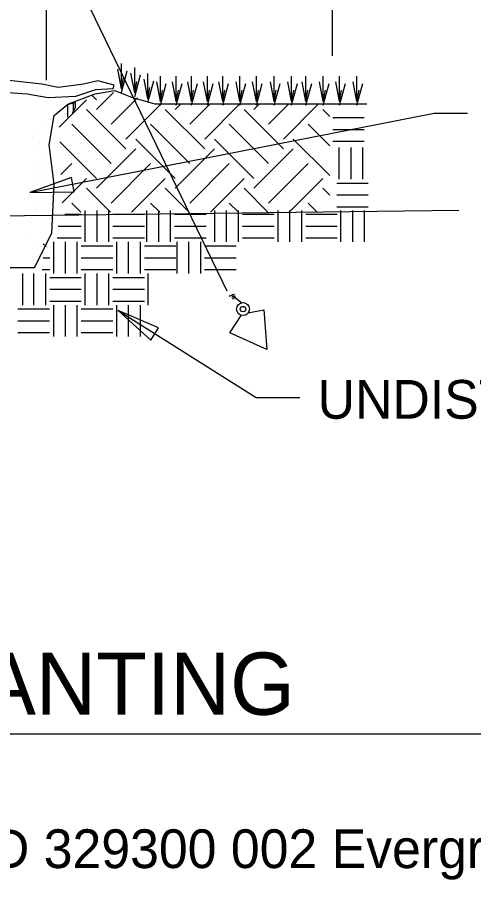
# Model space of a CAD drawing. Extents: x 10082 to 10257, y 10014 to 10069.
# Drawn here: x 10139.41 to 10147.66, y 10014.41 to 10029.99 of the extents above; entities that cross this region are included whole.
import ezdxf

# ---------------------------------------------------------------- set-up
doc = ezdxf.new("R2010")
doc.units = 0
for name, color, linetype in [('Default', 7, 'Continuous'), ('G-ANNO-CELL', 7, 'Continuous'), ('G-ANNO-TEXT', 7, 'Continuous'), ('G-DETL-GRID', 7, 'Continuous'), ('G-DETL-LINE', 7, 'Continuous'), ('G-DETL-OTLN', 7, 'Continuous'), ('G-DETL-PATT', 7, 'Continuous'), ('G-DETL-TEXT', 7, 'Continuous')]:
    doc.layers.add(name, color=color, linetype=linetype)

msp = doc.modelspace()

# ---------------------------------------------------------------- linework, layer by layer
at = {"layer": 'Default'}
for p, q in [((10139.933, 10028.854), (10139.933, 10030.362)), ((10145.108, 10029.298), (10145.108, 10030.362)), ((10139.636, 10026.823), (10146.946, 10028.258)), ((10146.946, 10028.258), (10147.547, 10028.258)), ((10138.67, 10026.397), (10147.389, 10026.507)), ((10141.228, 10024.692), (10143.727, 10023.12)), ((10143.727, 10023.12), (10144.513, 10023.12))]:
    msp.add_line(p, q, dxfattribs=at)
for points in [[(10140.433, 10026.839), (10140.384, 10027.096), (10139.636, 10026.823)], [(10141.82, 10024.16), (10141.961, 10024.38), (10141.228, 10024.692)]]:
    msp.add_lwpolyline(points, close=True, dxfattribs=at)
at = {"layer": 'G-ANNO-TEXT'}
for p, q in [((10120.67, 10017.044), (10152.453, 10017.044)), ((10120.67, 10017.044), (10152.453, 10017.044)), ((10122.114, 10017.044), (10151.008, 10017.044)), ((10122.114, 10017.044), (10151.008, 10017.044))]:
    msp.add_line(p, q, dxfattribs=at)
at = {"layer": 'G-DETL-LINE'}
for p, q in [((10137.65, 10036.497), (10143.193, 10025.048)), ((10141.291, 10028.7), (10141.224, 10029.053)), ((10141.291, 10028.7), (10141.291, 10029.158)), ((10141.53, 10028.628), (10141.53, 10029.086)), ((10141.291, 10028.633), (10141.396, 10029.024)), ((10141.291, 10028.7), (10141.329, 10028.901)), ((10141.53, 10028.628), (10141.462, 10028.981)), ((10141.53, 10028.561), (10141.635, 10028.952)), ((10141.769, 10028.52), (10141.769, 10028.978)), ((10141.995, 10028.472), (10141.995, 10028.93)), ((10142.281, 10028.472), (10142.281, 10028.93)), ((10142.557, 10028.472), (10142.557, 10028.93)), ((10142.843, 10028.472), (10142.843, 10028.93)), ((10143.12, 10028.472), (10143.12, 10028.93)), ((10143.433, 10028.472), (10143.433, 10028.93)), ((10143.729, 10028.472), (10143.729, 10028.93)), ((10144.052, 10028.472), (10144.052, 10028.93)), ((10144.367, 10028.472), (10144.367, 10028.93)), ((10144.624, 10028.472), (10144.624, 10028.93)), ((10144.939, 10028.472), (10144.939, 10028.93)), ((10145.233, 10028.472), (10145.233, 10028.93)), ((10145.548, 10028.472), (10145.548, 10028.93)), ((10141.53, 10028.628), (10141.567, 10028.829)), ((10141.769, 10028.52), (10141.701, 10028.873)), ((10141.769, 10028.454), (10141.874, 10028.844)), ((10141.769, 10028.52), (10141.806, 10028.721)), ((10141.995, 10028.472), (10141.928, 10028.825)), ((10141.995, 10028.406), (10142.1, 10028.796)), ((10142.281, 10028.472), (10142.214, 10028.825)), ((10142.281, 10028.406), (10142.386, 10028.796)), ((10142.557, 10028.472), (10142.49, 10028.825)), ((10142.557, 10028.406), (10142.662, 10028.796)), ((10142.843, 10028.472), (10142.775, 10028.825)), ((10142.843, 10028.406), (10142.948, 10028.796)), ((10143.12, 10028.472), (10143.052, 10028.825)), ((10143.12, 10028.406), (10143.225, 10028.796)), ((10143.433, 10028.472), (10143.365, 10028.825)), ((10143.433, 10028.406), (10143.537, 10028.796)), ((10143.729, 10028.472), (10143.661, 10028.825)), ((10143.729, 10028.406), (10143.834, 10028.796)), ((10144.052, 10028.472), (10143.985, 10028.825)), ((10144.052, 10028.406), (10144.157, 10028.796)), ((10144.367, 10028.472), (10144.3, 10028.825)), ((10144.367, 10028.406), (10144.472, 10028.796)), ((10144.624, 10028.472), (10144.557, 10028.825)), ((10144.624, 10028.406), (10144.729, 10028.796)), ((10144.939, 10028.472), (10144.872, 10028.825)), ((10144.939, 10028.406), (10145.044, 10028.796)), ((10145.233, 10028.472), (10145.165, 10028.825)), ((10145.233, 10028.406), (10145.338, 10028.796)), ((10145.548, 10028.472), (10145.48, 10028.825)), ((10145.548, 10028.406), (10145.653, 10028.796)), ((10141.995, 10028.472), (10142.033, 10028.673)), ((10142.281, 10028.472), (10142.319, 10028.673)), ((10142.557, 10028.472), (10142.595, 10028.673)), ((10142.843, 10028.472), (10142.88, 10028.673)), ((10143.12, 10028.472), (10143.157, 10028.673)), ((10143.433, 10028.472), (10143.47, 10028.673)), ((10143.729, 10028.472), (10143.766, 10028.673)), ((10144.052, 10028.472), (10144.09, 10028.673)), ((10144.367, 10028.472), (10144.405, 10028.673)), ((10144.624, 10028.472), (10144.662, 10028.673)), ((10144.939, 10028.472), (10144.977, 10028.673)), ((10145.233, 10028.472), (10145.27, 10028.673)), ((10145.548, 10028.472), (10145.585, 10028.673))]:
    msp.add_line(p, q, dxfattribs=at)
for points in [[(10143.326, 10024.989), (10143.234, 10024.947)], [(10143.34, 10024.961), (10143.28, 10024.929)], [(10143.357, 10024.932), (10143.297, 10024.9)], [(10143.467, 10024.827), (10143.3, 10024.958)], [(10143.864, 10024.703), (10143.917, 10023.988), (10143.251, 10024.292), (10143.456, 10024.601)], [(10143.573, 10024.65), (10143.864, 10024.703)]]:
    msp.add_lwpolyline(points, dxfattribs=at)
for radius in [0.117, 0.0496]:
    msp.add_circle((10143.488, 10024.718), radius, dxfattribs=at)
at = {"layer": 'G-DETL-OTLN'}
for p, q in [((10140.333, 10028.427), (10140.813, 10028.607)), ((10140.813, 10028.607), (10141.173, 10028.667)), ((10141.173, 10028.667), (10141.473, 10028.547)), ((10140.074, 10028.217), (10140.322, 10028.421)), ((10141.473, 10028.547), (10141.896, 10028.427)), ((10141.896, 10028.427), (10145.726, 10028.427)), ((10139.986, 10027.686), (10140.074, 10028.217)), ((10140.074, 10026.977), (10139.986, 10027.686)), ((10140.029, 10026.091), (10140.074, 10026.977)), ((10139.72, 10025.472), (10140.029, 10026.091)), ((10136.884, 10025.472), (10139.72, 10025.472))]:
    msp.add_line(p, q, dxfattribs=at)
msp.add_lwpolyline([(10136.661, 10029.223), (10136.7, 10028.984), (10137.357, 10028.904), (10137.776, 10028.865), (10138.594, 10028.725), (10139.05, 10028.645), (10139.587, 10028.606), (10139.967, 10028.545), (10140.465, 10028.565), (10140.824, 10028.684), (10141.141, 10028.705), (10141.161, 10028.764), (10140.864, 10028.844), (10140.603, 10028.785), (10140.145, 10028.725), (10139.848, 10028.785), (10139.31, 10028.844), (10138.812, 10028.904), (10138.274, 10029.025), (10137.657, 10029.025), (10137.08, 10029.143), (10136.879, 10029.203)], close=True, dxfattribs=at)
at = {"layer": 'G-DETL-PATT'}
for p, q in [((10140.838, 10028.503), (10140.763, 10028.578)), ((10140.838, 10028.325), (10141.144, 10028.631)), ((10140.164, 10028.007), (10140.66, 10028.503)), ((10140.322, 10028.185), (10140.322, 10028.421)), ((10140.333, 10028.42), (10140.451, 10028.453)), ((10140.423, 10028.298), (10140.423, 10028.445)), ((10140.451, 10028.453), (10140.451, 10028.353)), ((10141.104, 10028.058), (10141.581, 10028.535)), ((10141.371, 10027.792), (10142, 10028.42)), ((10142.261, 10028.325), (10142.355, 10028.42)), ((10142.528, 10028.058), (10142.889, 10028.42)), ((10142.795, 10027.792), (10143.423, 10028.42)), ((10143.685, 10028.325), (10143.779, 10028.42)), ((10143.951, 10028.058), (10144.313, 10028.42)), ((10144.218, 10027.792), (10144.847, 10028.42)), ((10140.451, 10028.353), (10140.399, 10028.251)), ((10141.371, 10027.614), (10140.66, 10028.325)), ((10142.795, 10027.614), (10142.083, 10028.325)), ((10144.218, 10027.614), (10143.507, 10028.325)), ((10145.056, 10028.2), (10144.93, 10028.325)), ((10145.109, 10028.18), (10145.68, 10028.18)), ((10139.851, 10027.999), (10139.851, 10027.999)), ((10141.104, 10027.347), (10140.393, 10028.058)), ((10142.528, 10027.347), (10141.816, 10028.058)), ((10143.951, 10027.347), (10143.24, 10028.058)), ((10145.056, 10027.666), (10144.663, 10028.058)), ((10145.109, 10027.966), (10145.68, 10027.966)), ((10139.683, 10027.817), (10139.683, 10027.817)), ((10139.753, 10027.906), (10139.753, 10027.906)), ((10140.067, 10027.786), (10140.067, 10027.786)), ((10142.261, 10027.08), (10141.549, 10027.792)), ((10143.685, 10027.08), (10142.973, 10027.792)), ((10145.056, 10027.132), (10144.396, 10027.792)), ((10139.799, 10027.71), (10139.799, 10027.71)), ((10139.996, 10027.753), (10139.996, 10027.753)), ((10140.838, 10027.08), (10140.174, 10027.743)), ((10145.109, 10027.752), (10145.68, 10027.752)), ((10145.228, 10027.068), (10145.228, 10027.639)), ((10145.442, 10027.068), (10145.442, 10027.639)), ((10145.656, 10027.068), (10145.656, 10027.639)), ((10139.724, 10027.596), (10139.724, 10027.596)), ((10140.838, 10026.902), (10141.549, 10027.614)), ((10142.261, 10026.902), (10142.973, 10027.614)), ((10143.685, 10026.902), (10144.396, 10027.614)), ((10139.799, 10027.355), (10139.799, 10027.355)), ((10139.822, 10027.473), (10139.822, 10027.473)), ((10139.961, 10027.327), (10139.961, 10027.327)), ((10140.197, 10027.151), (10140.393, 10027.347)), ((10141.104, 10026.635), (10141.816, 10027.347)), ((10142.528, 10026.635), (10143.24, 10027.347)), ((10143.951, 10026.635), (10144.663, 10027.347)), ((10139.953, 10027.167), (10139.953, 10027.167)), ((10139.684, 10027.088), (10139.684, 10027.088)), ((10139.754, 10027.159), (10139.754, 10027.159)), ((10139.926, 10027.111), (10139.926, 10027.111)), ((10140.06, 10027.052), (10140.06, 10027.052)), ((10140.067, 10027.039), (10140.067, 10027.039)), ((10140.218, 10026.638), (10140.66, 10027.08)), ((10141.474, 10026.47), (10142.083, 10027.08)), ((10142.897, 10026.47), (10143.507, 10027.08)), ((10144.321, 10026.47), (10144.93, 10027.08)), ((10139.883, 10026.87), (10139.883, 10026.87)), ((10141.091, 10026.47), (10140.66, 10026.902)), ((10142.515, 10026.47), (10142.083, 10026.902)), ((10143.938, 10026.47), (10143.507, 10026.902)), ((10145.056, 10026.776), (10144.93, 10026.902)), ((10145.183, 10026.997), (10145.753, 10026.997)), ((10139.901, 10026.73), (10139.901, 10026.73)), ((10140.038, 10026.818), (10140.038, 10026.818)), ((10145.183, 10026.783), (10145.753, 10026.783)), ((10139.76, 10026.609), (10139.76, 10026.609)), ((10140.051, 10026.58), (10140.051, 10026.58)), ((10140.557, 10026.47), (10140.393, 10026.635)), ((10141.981, 10026.47), (10141.816, 10026.635)), ((10143.404, 10026.47), (10143.24, 10026.635)), ((10144.828, 10026.47), (10144.663, 10026.635)), ((10145.183, 10026.569), (10145.753, 10026.569)), ((10139.749, 10026.533), (10139.749, 10026.533)), ((10139.755, 10026.412), (10139.755, 10026.412)), ((10139.756, 10026.477), (10139.756, 10026.477)), ((10139.987, 10026.405), (10139.987, 10026.405)), ((10140.266, 10026.432), (10140.564, 10026.432)), ((10140.635, 10025.933), (10140.635, 10026.503)), ((10140.849, 10025.933), (10140.849, 10026.503)), ((10141.063, 10025.933), (10141.063, 10026.503)), ((10141.134, 10026.432), (10141.704, 10026.432)), ((10141.75, 10025.933), (10141.75, 10026.503)), ((10141.964, 10025.933), (10141.964, 10026.503)), ((10142.178, 10025.933), (10142.178, 10026.503)), ((10142.249, 10026.432), (10142.82, 10026.432)), ((10142.978, 10025.933), (10142.978, 10026.503)), ((10143.192, 10025.933), (10143.192, 10026.503)), ((10143.406, 10025.933), (10143.406, 10026.503)), ((10143.478, 10026.432), (10144.048, 10026.432)), ((10144.122, 10025.933), (10144.122, 10026.503)), ((10144.336, 10025.933), (10144.336, 10026.503)), ((10144.55, 10025.933), (10144.55, 10026.503)), ((10144.621, 10026.432), (10145.191, 10026.432)), ((10145.257, 10025.933), (10145.257, 10026.503)), ((10145.471, 10025.933), (10145.471, 10026.503)), ((10145.685, 10025.933), (10145.685, 10026.503)), ((10139.65, 10026.276), (10139.65, 10026.276)), ((10140.055, 10026.334), (10140.055, 10026.334)), ((10140.068, 10026.292), (10140.068, 10026.292)), ((10140.069, 10026.357), (10140.069, 10026.357)), ((10140.147, 10026.218), (10140.564, 10026.218)), ((10141.134, 10026.218), (10141.704, 10026.218)), ((10142.249, 10026.218), (10142.82, 10026.218)), ((10143.478, 10026.218), (10144.048, 10026.218)), ((10144.621, 10026.218), (10145.191, 10026.218)), ((10139.655, 10025.972), (10139.655, 10025.972)), ((10139.979, 10025.986), (10139.979, 10025.986)), ((10140.065, 10025.362), (10140.065, 10025.933)), ((10140.126, 10026.004), (10140.564, 10026.004)), ((10140.278, 10025.362), (10140.278, 10025.933)), ((10140.492, 10025.362), (10140.492, 10025.933)), ((10141.134, 10026.004), (10141.704, 10026.004)), ((10141.205, 10025.362), (10141.205, 10025.933)), ((10141.419, 10025.362), (10141.419, 10025.933)), ((10141.633, 10025.362), (10141.633, 10025.933)), ((10142.249, 10026.004), (10142.82, 10026.004)), ((10142.295, 10025.362), (10142.295, 10025.933)), ((10142.509, 10025.362), (10142.509, 10025.933)), ((10142.723, 10025.362), (10142.723, 10025.933)), ((10143.478, 10026.004), (10144.048, 10026.004)), ((10144.621, 10026.004), (10145.191, 10026.004)), ((10139.72, 10025.863), (10139.72, 10025.863)), ((10139.812, 10025.893), (10139.812, 10025.893)), ((10139.927, 10025.849), (10139.877, 10025.899)), ((10139.948, 10025.84), (10139.948, 10025.84)), ((10140.564, 10025.861), (10141.134, 10025.861)), ((10141.704, 10025.861), (10142.275, 10025.861)), ((10142.794, 10025.861), (10143.364, 10025.861)), ((10139.685, 10025.675), (10139.685, 10025.675)), ((10139.755, 10025.665), (10139.755, 10025.665)), ((10139.875, 10025.647), (10139.993, 10025.647)), ((10140.564, 10025.647), (10141.134, 10025.647)), ((10141.704, 10025.647), (10142.275, 10025.647)), ((10142.794, 10025.647), (10143.364, 10025.647)), ((10139.793, 10025.593), (10139.793, 10025.593)), ((10139.509, 10024.792), (10139.509, 10025.362)), ((10139.708, 10024.792), (10139.708, 10025.362)), ((10139.854, 10025.434), (10139.993, 10025.434)), ((10139.922, 10024.792), (10139.922, 10025.362)), ((10140.564, 10025.434), (10141.134, 10025.434)), ((10140.635, 10024.792), (10140.635, 10025.362)), ((10140.849, 10024.792), (10140.849, 10025.362)), ((10141.063, 10024.792), (10141.063, 10025.362)), ((10141.704, 10025.434), (10142.275, 10025.434)), ((10141.776, 10024.792), (10141.776, 10025.362)), ((10142.794, 10025.434), (10143.364, 10025.434)), ((10139.993, 10025.291), (10140.564, 10025.291)), ((10141.134, 10025.291), (10141.704, 10025.291)), ((10139.993, 10025.077), (10140.564, 10025.077)), ((10141.134, 10025.077), (10141.704, 10025.077)), ((10139.993, 10024.863), (10140.564, 10024.863)), ((10141.134, 10024.863), (10141.704, 10024.863)), ((10139.418, 10024.721), (10139.988, 10024.721)), ((10140.065, 10024.221), (10140.065, 10024.792)), ((10140.278, 10024.221), (10140.278, 10024.792)), ((10140.492, 10024.221), (10140.492, 10024.792)), ((10140.564, 10024.721), (10141.134, 10024.721)), ((10141.205, 10024.221), (10141.205, 10024.792)), ((10141.419, 10024.221), (10141.419, 10024.792)), ((10141.633, 10024.221), (10141.633, 10024.792)), ((10139.418, 10024.507), (10139.988, 10024.507)), ((10140.564, 10024.507), (10141.134, 10024.507)), ((10139.418, 10024.293), (10139.988, 10024.293)), ((10140.564, 10024.293), (10141.134, 10024.293))]:
    msp.add_line(p, q, dxfattribs=at)

# ---------------------------------------------------------------- texts
at = {"layer": 'G-ANNO-CELL'}
msp.add_text('MD 329300 002 Evergreen Planting 7/27/18', height=0.7, dxfattribs=at).set_placement((10138.169, 10014.618))
at = {"layer": 'G-DETL-GRID'}
msp.add_text('EVERGREEN PLANTING', height=1.125, dxfattribs=at).set_placement((10127.037, 10017.388))
at = {"layer": 'G-DETL-TEXT'}
msp.add_text('UNDISTURBED SOIL', height=0.7, dxfattribs=at).set_placement((10144.837, 10022.738))

doc.saveas('drawing.dxf')
